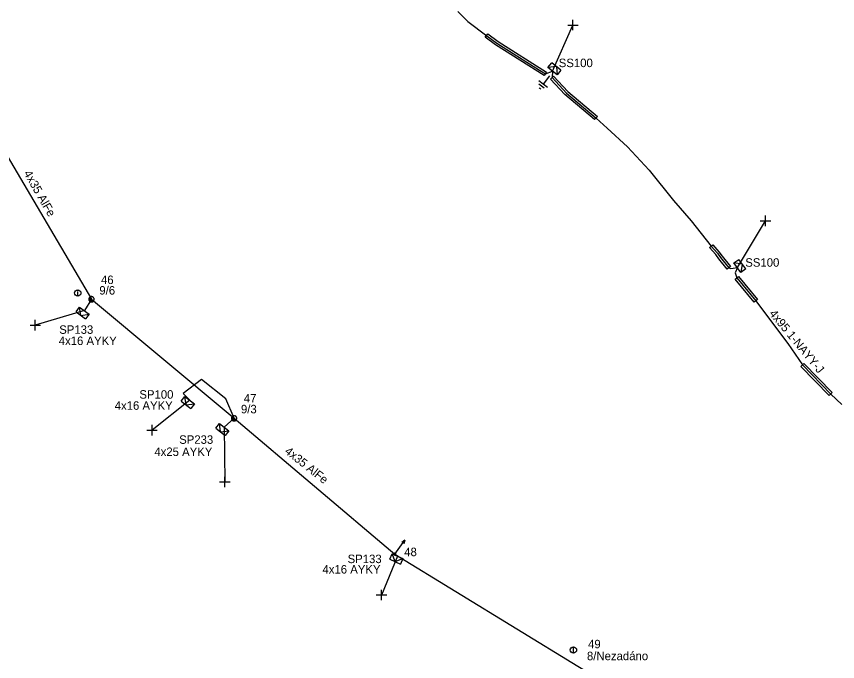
# Model space of a CAD drawing. Extents: x -748492 to -735633, y -1146251 to -1139940.
# Drawn here: x -736671.1 to -736574.3, y -1143470.7 to -1143394.6 of the extents above; entities that cross this region are included whole.
import ezdxf

# ---------------------------------------------------------------- set-up
doc = ezdxf.new("R2010")
doc.units = 0
for name, color, linetype in [('Vrstva 1', 7, 'Continuous'), ('Vrstva 10', 7, 'Continuous'), ('Vrstva 12', 7, 'Continuous'), ('Vrstva 13', 7, 'Continuous'), ('Vrstva 14', 7, 'Continuous'), ('Vrstva 15', 7, 'Continuous'), ('Vrstva 2', 7, 'Continuous'), ('Vrstva 20', 7, 'Continuous'), ('Vrstva 31', 7, 'Continuous'), ('Vrstva 33', 7, 'Continuous'), ('Vrstva 34', 7, 'Continuous'), ('Vrstva 36', 7, 'Continuous'), ('Vrstva 5', 7, 'Continuous'), ('Vrstva 52', 7, 'Continuous'), ('Vrstva 54', 7, 'Continuous'), ('Vrstva 59', 7, 'Continuous'), ('Vrstva 6', 7, 'Continuous'), ('Vrstva 9', 7, 'Continuous')]:
    doc.layers.add(name, color=color, linetype=linetype)

# ---------------------------------------------------------------- blocks, each defined once
blk = doc.blocks.new('NN440')
at = {"layer": 'Vrstva 2'}
for points in [[(0.63, 0), (0.63, 0.06), (0.62, 0.13), (0.6, 0.19), (0.58, 0.25), (0.55, 0.31), (0.51, 0.37), (0.47, 0.42), (0.42, 0.46), (0.37, 0.51), (0.32, 0.54), (0.26, 0.57), (0.2, 0.59), (0.13, 0.61), (0.07, 0.62), (0, 0.63), (-0.06, 0.62), (-0.13, 0.61), (-0.19, 0.59), (-0.26, 0.57), (-0.31, 0.54), (-0.37, 0.51), (-0.42, 0.46), (-0.47, 0.42), (-0.51, 0.37), (-0.54, 0.31), (-0.57, 0.25), (-0.6, 0.19), (-0.62, 0.13), (-0.63, 0.06), (-0.63, 0), (-0.63, -0.07), (-0.62, -0.14), (-0.6, -0.2), (-0.57, -0.26), (-0.54, -0.32), (-0.51, -0.37), (-0.47, -0.43), (-0.42, -0.47), (-0.37, -0.51), (-0.31, -0.55), (-0.26, -0.58), (-0.19, -0.6), (-0.13, -0.62), (-0.06, -0.63), (0, -0.63), (0.07, -0.63), (0.13, -0.62), (0.2, -0.6), (0.26, -0.58), (0.32, -0.55), (0.37, -0.51), (0.42, -0.47), (0.47, -0.43), (0.51, -0.37), (0.55, -0.32), (0.58, -0.26), (0.6, -0.2), (0.62, -0.14), (0.63, -0.07), (0.63, 0)], [(-0.63, 0), (0.63, 0)], [(-0.6, -0.18), (0.57, -0.18)], [(-0.51, -0.32), (0.5, -0.32)], [(-0.37, -0.47), (0.35, -0.47)]]:
    blk.add_lwpolyline(points, dxfattribs=at)
blk = doc.blocks.new('NN560')
at = {"layer": 'Vrstva 2'}
for points in [[(1.999, -0.001), (1.59, 0.141)], [(0, -0.001), (1.999, -0.001)], [(1.999, -0.001), (1.59, -0.134)]]:
    blk.add_lwpolyline(points, dxfattribs=at)
blk = doc.blocks.new('NN770')
at = {"layer": 'Vrstva 10'}
for p, q in [((0.002, 0.187), (0.002, 0.263)), ((0.002, -0.276), (0.002, 0.111))]:
    blk.add_line(p, q, dxfattribs=at)
blk.add_circle((0, -0.008), 0.375, dxfattribs=at)
blk = doc.blocks.new('NN800')
at = {"layer": 'Vrstva 1'}
for points in [[(-0.442, 0.442), (0.442, -0.442)], [(-0.442, -0.442), (0.442, 0.442)]]:
    blk.add_lwpolyline(points, dxfattribs=at)
blk = doc.blocks.new('NN630')
at = {"layer": 'Vrstva 9'}
for points in [[(-0.003, -0.7), (-0.703, 0)], [(-0.703, -0.7), (-0.703, 0), (0.697, 0), (0.697, -0.7)], [(-0.703, -0.7), (0.697, -0.7)], [(-0.003, -0.7), (0.697, 0)]]:
    blk.add_lwpolyline(points, dxfattribs=at)
blk = doc.blocks.new('NN810')
at = {"layer": 'Vrstva 14'}
for points in [[(0.004, -0.64), (0.004, -1.89)], [(0.629, -1.89), (-0.621, -1.89)], [(0.388, -2.2), (-0.399, -2.2)], [(0.004, -2.515), (-0.124, -2.515)], [(0.137, -2.515), (0.004, -2.515)]]:
    blk.add_lwpolyline(points, dxfattribs=at)
blk = doc.blocks.new('NN500')
at = {"layer": 'Vrstva 2'}
for points in [[(0, -0.24), (0.02, -0.23), (0.05, -0.23), (0.07, -0.22), (0.09, -0.22), (0.12, -0.2), (0.14, -0.19), (0.16, -0.18), (0.17, -0.16), (0.19, -0.14), (0.2, -0.12), (0.21, -0.1), (0.22, -0.07), (0.23, -0.05), (0.23, -0.02), (0.23, 0), (0.23, 0.02), (0.23, 0.05), (0.22, 0.07), (0.21, 0.1), (0.2, 0.12), (0.19, 0.14), (0.17, 0.16), (0.16, 0.17), (0.14, 0.19), (0.12, 0.2), (0.09, 0.21), (0.07, 0.22), (0.05, 0.23), (0.02, 0.23), (0, 0.23), (-0.03, 0.23), (-0.05, 0.23), (-0.07, 0.22), (-0.1, 0.21), (-0.12, 0.2), (-0.14, 0.19), (-0.16, 0.17), (-0.18, 0.16), (-0.19, 0.14), (-0.2, 0.12), (-0.22, 0.1), (-0.22, 0.07), (-0.23, 0.05), (-0.23, 0.02), (-0.24, 0), (-0.23, -0.02), (-0.23, -0.05), (-0.22, -0.07), (-0.22, -0.1), (-0.2, -0.12), (-0.19, -0.14), (-0.18, -0.16), (-0.16, -0.18), (-0.14, -0.19), (-0.12, -0.2), (-0.1, -0.22), (-0.07, -0.22), (-0.05, -0.23), (-0.03, -0.23), (0, -0.24)], [(0, -0.24), (0.02, -0.23), (0.05, -0.23), (0.07, -0.22), (0.09, -0.22), (0.12, -0.2), (0.14, -0.19), (0.16, -0.18), (0.17, -0.16), (0.19, -0.14), (0.2, -0.12), (0.21, -0.1), (0.22, -0.07), (0.23, -0.05), (0.23, -0.02), (0.23, 0), (0.23, 0.02), (0.23, 0.05), (0.22, 0.07), (0.21, 0.1), (0.2, 0.12), (0.19, 0.14), (0.17, 0.16), (0.16, 0.17), (0.14, 0.19), (0.12, 0.2), (0.09, 0.21), (0.07, 0.22), (0.05, 0.23), (0.02, 0.23), (0, 0.23), (-0.03, 0.23), (-0.05, 0.23), (-0.07, 0.22), (-0.1, 0.21), (-0.12, 0.2), (-0.14, 0.19), (-0.16, 0.17), (-0.18, 0.16), (-0.19, 0.14), (-0.2, 0.12), (-0.22, 0.1), (-0.22, 0.07), (-0.23, 0.05), (-0.23, 0.02), (-0.24, 0), (-0.23, -0.02), (-0.23, -0.05), (-0.22, -0.07), (-0.22, -0.1), (-0.2, -0.12), (-0.19, -0.14), (-0.18, -0.16), (-0.16, -0.18), (-0.14, -0.19), (-0.12, -0.2), (-0.1, -0.22), (-0.07, -0.22), (-0.05, -0.23), (-0.03, -0.23), (0, -0.24)], [(0, -0.21), (0.02, -0.2), (0.04, -0.2), (0.06, -0.2), (0.08, -0.19), (0.1, -0.18), (0.12, -0.17), (0.14, -0.15), (0.15, -0.14), (0.16, -0.12), (0.18, -0.1), (0.19, -0.08), (0.19, -0.06), (0.2, -0.04), (0.2, -0.02), (0.2, 0), (0.2, 0.02), (0.2, 0.04), (0.19, 0.06), (0.19, 0.08), (0.18, 0.1), (0.16, 0.12), (0.15, 0.14), (0.14, 0.15), (0.12, 0.17), (0.1, 0.18), (0.08, 0.19), (0.06, 0.19), (0.04, 0.2), (0.02, 0.2), (0, 0.2), (-0.02, 0.2), (-0.04, 0.2), (-0.06, 0.19), (-0.08, 0.19), (-0.1, 0.18), (-0.12, 0.17), (-0.14, 0.15), (-0.15, 0.14), (-0.17, 0.12), (-0.18, 0.1), (-0.19, 0.08), (-0.2, 0.06), (-0.2, 0.04), (-0.21, 0.02), (-0.21, 0), (-0.21, -0.02), (-0.2, -0.04), (-0.2, -0.06), (-0.19, -0.08), (-0.18, -0.1), (-0.17, -0.12), (-0.15, -0.14), (-0.14, -0.15), (-0.12, -0.17), (-0.1, -0.18), (-0.08, -0.19), (-0.06, -0.2), (-0.04, -0.2), (-0.02, -0.2), (0, -0.21)], [(0, -0.18), (0.02, -0.18), (0.04, -0.17), (0.05, -0.17), (0.07, -0.16), (0.09, -0.15), (0.1, -0.14), (0.12, -0.13), (0.13, -0.12), (0.14, -0.1), (0.15, -0.09), (0.16, -0.07), (0.17, -0.05), (0.17, -0.04), (0.17, -0.02), (0.17, 0), (0.17, 0.02), (0.17, 0.04), (0.17, 0.05), (0.16, 0.07), (0.15, 0.09), (0.14, 0.1), (0.13, 0.12), (0.12, 0.13), (0.1, 0.14), (0.09, 0.15), (0.07, 0.16), (0.05, 0.17), (0.04, 0.17), (0.02, 0.17), (0, 0.18), (-0.02, 0.17), (-0.04, 0.17), (-0.06, 0.17), (-0.07, 0.16), (-0.09, 0.15), (-0.1, 0.14), (-0.12, 0.13), (-0.13, 0.12), (-0.14, 0.1), (-0.15, 0.09), (-0.16, 0.07), (-0.17, 0.05), (-0.17, 0.04), (-0.18, 0.02), (-0.18, 0), (-0.18, -0.02), (-0.17, -0.04), (-0.17, -0.05), (-0.16, -0.07), (-0.15, -0.09), (-0.14, -0.1), (-0.13, -0.12), (-0.12, -0.13), (-0.1, -0.14), (-0.09, -0.15), (-0.07, -0.16), (-0.06, -0.17), (-0.04, -0.17), (-0.02, -0.18), (0, -0.18)], [(0, -0.15), (0.01, -0.15), (0.03, -0.14), (0.04, -0.14), (0.06, -0.13), (0.07, -0.13), (0.08, -0.12), (0.1, -0.11), (0.11, -0.1), (0.12, -0.09), (0.13, -0.07), (0.13, -0.06), (0.14, -0.05), (0.14, -0.03), (0.14, -0.02), (0.14, 0), (0.14, 0.01), (0.14, 0.03), (0.14, 0.04), (0.13, 0.06), (0.13, 0.07), (0.12, 0.09), (0.11, 0.1), (0.1, 0.11), (0.08, 0.12), (0.07, 0.13), (0.06, 0.13), (0.04, 0.14), (0.03, 0.14), (0.01, 0.14), (0, 0.15), (-0.02, 0.14), (-0.03, 0.14), (-0.05, 0.14), (-0.06, 0.13), (-0.07, 0.13), (-0.09, 0.12), (-0.1, 0.11), (-0.11, 0.1), (-0.12, 0.09), (-0.13, 0.07), (-0.13, 0.06), (-0.14, 0.04), (-0.14, 0.03), (-0.15, 0.01), (-0.15, 0), (-0.15, -0.02), (-0.14, -0.03), (-0.14, -0.05), (-0.13, -0.06), (-0.13, -0.07), (-0.12, -0.09), (-0.11, -0.1), (-0.1, -0.11), (-0.09, -0.12), (-0.07, -0.13), (-0.06, -0.13), (-0.05, -0.14), (-0.03, -0.14), (-0.02, -0.15), (0, -0.15)], [(0, -0.12), (0.01, -0.12), (0.02, -0.11), (0.03, -0.11), (0.05, -0.11), (0.06, -0.1), (0.07, -0.09), (0.08, -0.09), (0.09, -0.08), (0.09, -0.07), (0.1, -0.06), (0.11, -0.05), (0.11, -0.04), (0.11, -0.02), (0.11, -0.01), (0.12, 0), (0.11, 0.01), (0.11, 0.02), (0.11, 0.04), (0.11, 0.05), (0.1, 0.06), (0.09, 0.07), (0.09, 0.08), (0.08, 0.09), (0.07, 0.09), (0.06, 0.1), (0.05, 0.11), (0.03, 0.11), (0.02, 0.11), (0.01, 0.12), (0, 0.12), (-0.01, 0.12), (-0.03, 0.11), (-0.04, 0.11), (-0.05, 0.11), (-0.06, 0.1), (-0.07, 0.09), (-0.08, 0.09), (-0.09, 0.08), (-0.1, 0.07), (-0.1, 0.06), (-0.11, 0.05), (-0.11, 0.04), (-0.12, 0.02), (-0.12, 0.01), (-0.12, 0), (-0.12, -0.01), (-0.12, -0.02), (-0.11, -0.04), (-0.11, -0.05), (-0.1, -0.06), (-0.1, -0.07), (-0.09, -0.08), (-0.08, -0.09), (-0.07, -0.09), (-0.06, -0.1), (-0.05, -0.11), (-0.04, -0.11), (-0.03, -0.11), (-0.01, -0.12), (0, -0.12)], [(0, -0.09), (0.01, -0.09), (0.02, -0.09), (0.03, -0.08), (0.03, -0.08), (0.04, -0.08), (0.05, -0.07), (0.06, -0.07), (0.06, -0.06), (0.07, -0.05), (0.07, -0.04), (0.08, -0.04), (0.08, -0.03), (0.08, -0.02), (0.09, -0.01), (0.09, 0), (0.09, 0.01), (0.08, 0.02), (0.08, 0.03), (0.08, 0.03), (0.07, 0.04), (0.07, 0.05), (0.06, 0.06), (0.06, 0.06), (0.05, 0.07), (0.04, 0.07), (0.03, 0.08), (0.03, 0.08), (0.02, 0.08), (0.01, 0.09), (0, 0.09), (-0.01, 0.09), (-0.02, 0.08), (-0.03, 0.08), (-0.04, 0.08), (-0.04, 0.07), (-0.05, 0.07), (-0.06, 0.06), (-0.07, 0.06), (-0.07, 0.05), (-0.08, 0.04), (-0.08, 0.03), (-0.08, 0.03), (-0.09, 0.02), (-0.09, 0.01), (-0.09, 0), (-0.09, -0.01), (-0.09, -0.02), (-0.08, -0.03), (-0.08, -0.04), (-0.08, -0.04), (-0.07, -0.05), (-0.07, -0.06), (-0.06, -0.07), (-0.05, -0.07), (-0.04, -0.08), (-0.04, -0.08), (-0.03, -0.08), (-0.02, -0.09), (-0.01, -0.09), (0, -0.09)], [(0, -0.06), (0, -0.06), (0.01, -0.06), (0.02, -0.05), (0.02, -0.05), (0.03, -0.05), (0.03, -0.05), (0.04, -0.04), (0.04, -0.04), (0.05, -0.03), (0.05, -0.03), (0.05, -0.02), (0.05, -0.02), (0.05, -0.01), (0.06, -0.01), (0.06, 0), (0.06, 0.01), (0.05, 0.01), (0.05, 0.02), (0.05, 0.02), (0.05, 0.03), (0.05, 0.03), (0.04, 0.04), (0.04, 0.04), (0.03, 0.05), (0.03, 0.05), (0.02, 0.05), (0.02, 0.05), (0.01, 0.06), (0, 0.06), (0, 0.06), (-0.01, 0.06), (-0.01, 0.06), (-0.02, 0.05), (-0.02, 0.05), (-0.03, 0.05), (-0.03, 0.05), (-0.04, 0.04), (-0.04, 0.04), (-0.05, 0.03), (-0.05, 0.03), (-0.05, 0.02), (-0.06, 0.02), (-0.06, 0.01), (-0.06, 0.01), (-0.06, 0), (-0.06, -0.01), (-0.06, -0.01), (-0.06, -0.02), (-0.05, -0.02), (-0.05, -0.03), (-0.05, -0.03), (-0.04, -0.04), (-0.04, -0.04), (-0.03, -0.05), (-0.03, -0.05), (-0.02, -0.05), (-0.02, -0.05), (-0.01, -0.06), (-0.01, -0.06), (0, -0.06)], [(0, -0.03), (0, -0.03), (0, -0.03), (0.01, -0.03), (0.01, -0.03), (0.01, -0.02), (0.02, -0.02), (0.02, -0.02), (0.02, -0.02), (0.02, -0.02), (0.02, -0.01), (0.02, -0.01), (0.03, -0.01), (0.03, -0.01), (0.03, 0), (0.03, 0), (0.03, 0), (0.03, 0.01), (0.03, 0.01), (0.02, 0.01), (0.02, 0.01), (0.02, 0.02), (0.02, 0.02), (0.02, 0.02), (0.02, 0.02), (0.01, 0.02), (0.01, 0.02), (0.01, 0.03), (0, 0.03), (0, 0.03), (0, 0.03), (0, 0.03), (-0.01, 0.03), (-0.01, 0.03), (-0.01, 0.02), (-0.02, 0.02), (-0.02, 0.02), (-0.02, 0.02), (-0.02, 0.02), (-0.02, 0.02), (-0.03, 0.01), (-0.03, 0.01), (-0.03, 0.01), (-0.03, 0.01), (-0.03, 0), (-0.03, 0), (-0.03, 0), (-0.03, -0.01), (-0.03, -0.01), (-0.03, -0.01), (-0.03, -0.01), (-0.02, -0.02), (-0.02, -0.02), (-0.02, -0.02), (-0.02, -0.02), (-0.02, -0.02), (-0.01, -0.03), (-0.01, -0.03), (-0.01, -0.03), (0, -0.03), (0, -0.03)], [(0.23, 0), (0.7, 0)]]:
    blk.add_lwpolyline(points, dxfattribs=at)

msp = doc.modelspace()

# ---------------------------------------------------------------- linework, layer by layer
at = {"layer": 'Vrstva 1'}
msp.add_lwpolyline([(-736676.261, -1143404.169), (-736662.23, -1143427.97), (-736645.42, -1143442.01), (-736626.46, -1143458.019), (-736604.89, -1143471.26), (-736581.85, -1143485.04)], dxfattribs=at)
at = {"layer": 'Vrstva 20'}
for points in [[(-736615.511, -1143396.669), (-736614.313, -1143397.555), (-736608.595, -1143401.17), (-736608.865, -1143401.59), (-736614.611, -1143397.957), (-736615.809, -1143397.071)], [(-736607.757, -1143401.659), (-736606.077, -1143403.46), (-736602.599, -1143406.399), (-736602.921, -1143406.781), (-736606.443, -1143403.801), (-736608.123, -1143402)], [(-736588.991, -1143421.546), (-736588.279, -1143422.368), (-736587.901, -1143422.888), (-736586.906, -1143424.112), (-736587.294, -1143424.428), (-736588.299, -1143423.192), (-736588.656, -1143422.695), (-736589.368, -1143421.873)], [(-736585.967, -1143425.281), (-736583.737, -1143427.981), (-736584.123, -1143428.299), (-736586.353, -1143425.599)], [(-736578.251, -1143435.546), (-736574.911, -1143438.976), (-736575.269, -1143439.324), (-736578.609, -1143435.894)]]:
    msp.add_lwpolyline(points, close=True, dxfattribs=at)
at = {"layer": 'Vrstva 5'}
msp.add_lwpolyline([(-736619.035, -1143394.042), (-736617.89, -1143395.22), (-736615.635, -1143396.892), (-736614.47, -1143397.75), (-736609.405, -1143400.952), (-736608.73, -1143401.38), (-736607.879, -1143401.07), (-736607.94, -1143401.83), (-736606.245, -1143403.642), (-736602.735, -1143406.612), (-736601.45, -1143407.8), (-736599.07, -1143409.97), (-736596.48, -1143412.73), (-736593.61, -1143416.3), (-736591.53, -1143418.71), (-736589.18, -1143421.71), (-736588.46, -1143422.54), (-736588.1, -1143423.04), (-736587.1, -1143424.27), (-736586.87, -1143424.34), (-736586.09, -1143424.239), (-736586.37, -1143424.84), (-736586.16, -1143425.44), (-736583.93, -1143428.14), (-736582.55, -1143430.01), (-736580.16, -1143433.18), (-736578.43, -1143435.72), (-736575.065, -1143439.172), (-736573.77, -1143440.37)], dxfattribs=at)
at = {"layer": 'Vrstva 52'}
for points in [[(-736662.23, -1143427.97), (-736663.07, -1143429.31)], [(-736645.42, -1143442.01), (-736646.39, -1143439.7), (-736649.25, -1143437.45), (-736651.43, -1143439.08), (-736650.66, -1143439.87)], [(-736645.42, -1143442.01), (-736646.6, -1143443.06)], [(-736626.46, -1143458.02), (-736626.15, -1143458.27)]]:
    msp.add_lwpolyline(points, dxfattribs=at)
at = {"layer": 'Vrstva 59'}
for points in [[(-736607.88, -1143401.07), (-736605.477, -1143395.62)], [(-736586.09, -1143424.239), (-736582.789, -1143418.718)], [(-736663.07, -1143429.31), (-736668.856, -1143431.035)], [(-736650.66, -1143439.87), (-736655.097, -1143443.411)], [(-736646.6, -1143443.06), (-736646.517, -1143449.518)], [(-736626.15, -1143458.27), (-736628.063, -1143462.848)]]:
    msp.add_lwpolyline(points, dxfattribs=at)

# ---------------------------------------------------------------- block references
at = {"layer": 'Vrstva 13', "yscale": 0.5}
for name, p, xscale, rotation in [('NN440', (-736662.23, -1143427.97), 0.5, -40.54268634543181), ('NN440', (-736645.42, -1143442.01), 0.5, -39.228583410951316), ('NN500', (-736626.46, -1143458.02), 0.5000000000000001, 54.82777069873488)]:
    msp.add_blockref(name, p, dxfattribs=dict(at, xscale=xscale, rotation=rotation))
at = {"layer": 'Vrstva 13', "rotation": 54.83514334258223}
msp.add_blockref('NN560', (-736626.46, -1143458.019), dxfattribs=at)
at = {"layer": 'Vrstva 15', "rotation": -37.14358607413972}
msp.add_blockref('NN810', (-736607.854, -1143401.091), dxfattribs=at)
at = {"layer": 'Vrstva 31'}
for p, rotation in [((-736607.879, -1143401.07), 141.24231942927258), ((-736586.09, -1143424.239), 126.49671939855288), ((-736663.07, -1143429.31), -37.26222049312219), ((-736650.66, -1143439.87), -37.6871009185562), ((-736646.6, -1143443.06), -37.401174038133), ((-736626.15, -1143458.27), -24.41534572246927)]:
    msp.add_blockref('NN630', p, dxfattribs=dict(at, rotation=rotation))
at = {"layer": 'Vrstva 34'}
for p, rotation in [((-736605.477, -1143395.62), 44.99999995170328), ((-736582.789, -1143418.718), 45), ((-736668.856, -1143431.035), 45), ((-736655.097, -1143443.41), 44.99999995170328), ((-736646.517, -1143449.518), 45), ((-736628.063, -1143462.847), 45)]:
    msp.add_blockref('NN800', p, dxfattribs=dict(at, rotation=rotation))
at = {"layer": 'Vrstva 36'}
for p in [(-736663.853, -1143427.212), (-736605.426, -1143469.326)]:
    msp.add_blockref('NN770', p, dxfattribs=at)

# ---------------------------------------------------------------- texts
at = {"layer": 'Vrstva 12'}
for s, p in [('9/6', (-736661.307, -1143427.416)), ('9/3', (-736644.616, -1143441.42)), ('8/Nezadáno', (-736603.829, -1143470.538))]:
    msp.add_text(s, height=1, dxfattribs=at).set_placement(p)
at = {"layer": 'Vrstva 14'}
for s, p in [('46', (-736661.116, -1143426.172)), ('47', (-736644.279, -1143440.141)), ('48', (-736625.371, -1143458.269)), ('49', (-736603.7, -1143469.134))]:
    msp.add_text(s, height=1, dxfattribs=at).set_placement(p)
at = {"layer": 'Vrstva 2'}
for rotation, p in [(299.805, (-736670.264, -1143413.107)), (321.471, (-736639.544, -1143446.053))]:
    msp.add_text('4x35 AlFe', height=1, rotation=rotation, dxfattribs=at).set_placement(p)
at = {"layer": 'Vrstva 33'}
for s, p in [('SS100', (-736607.155, -1143400.589)), ('SS100', (-736585.168, -1143424.129)), ('SP133', (-736666.038, -1143432.044)), ('SP100', (-736656.589, -1143439.691)), ('SP233', (-736651.897, -1143445.017)), ('SP133', (-736632.043, -1143459.087))]:
    msp.add_text(s, height=1, dxfattribs=at).set_placement(p)
at = {"layer": 'Vrstva 54'}
for s, p in [('4x16 AYKY', (-736666.093, -1143433.362)), ('4x16 AYKY', (-736659.497, -1143441.001)), ('4x25 AYKY', (-736654.822, -1143446.454)), ('4x16 AYKY', (-736635.006, -1143460.317))]:
    msp.add_text(s, height=1, dxfattribs=at).set_placement(p)
at = {"layer": 'Vrstva 6'}
msp.add_text('4x95 1-NAYY-J', height=1, rotation=309.554, dxfattribs=at).set_placement((-736582.412, -1143429.69))

doc.saveas('drawing.dxf')
